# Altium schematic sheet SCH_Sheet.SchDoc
size A; SheetNumber: 1; SheetTotal: 1
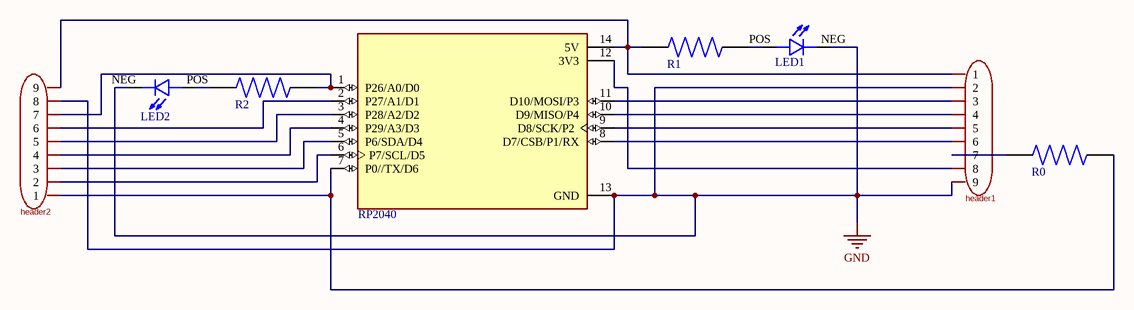
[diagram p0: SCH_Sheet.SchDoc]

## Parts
header1  2.54-1*9P母  [2.54-1*9]  (value not drawn)
header2  2.54-1*9P母  [2.54-1*9]  (value not drawn)
LED1  LHN974_RED_LED_1206  [LED2]  (value not drawn)
LED2  LHN974_RED_LED_1206  [LED2]  (value not drawn)
R0  1k  [1k]  (value not drawn)
R1  1k  [1k]  (value not drawn)
R2  1k  [1k]  (value not drawn)
RP2040  102010428  [102010428]  (value not drawn)

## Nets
GND: header1.2 header1.9 header2.8 LED1.NEG LED2.NEG RP2040.13(GND)
Netheader1_1: header1.1 header2.9 R1.1 RP2040.14(5V)
Netheader1_3: header1.3 RP2040.11(D10/MOSI/P3)
Netheader1_4: header1.4 RP2040.10(D9/MISO/P4)
Netheader1_5: header1.5 RP2040.9(D8/SCK/P2)
Netheader1_6: header1.6 RP2040.8(D7/CSB/P1/RX)
Netheader1_7: header1.7 R0.1
Netheader1_8: header1.8 RP2040.12(3V3)
Netheader2_1: header2.1 R0.2 RP2040.7(P0//TX/D6)
Netheader2_2: header2.2 RP2040.6(P7/SCL/D5)
Netheader2_3: header2.3 RP2040.5(P6/SDA/D4)
Netheader2_4: header2.4 RP2040.4(P29/A3/D3)
Netheader2_5: header2.5 RP2040.3(P28/A2/D2)
Netheader2_6: header2.6 RP2040.2(P27/A1/D1)
Netheader2_7: header2.7 R2.2 RP2040.1(P26/A0/D0)
NetLED1_POS: LED1.POS R1.2
NetLED2_POS: LED2.POS R2.1

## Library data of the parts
header1 header2 = 2.54-1*9: Manufacturer: BOOMELE(博穆精密); Symbol: Header-Female-2.54_1x9; Add into BOM: yes; Holes Structure: 1x9P; Pitch: 2.54mm; Number of Holes: 9P
LED1 LED2 = LED2: 2.6 V Red LED SMD; MP: LHN974 RED LED 1206; MF: Osram
R0-R2 = 1k: Res Thick Film 3.2 x 1.6 mm 6.8K Ohm 1% 0.25W(1/4W) 100ppm/ C Molded SMD Paper T/R; MP: RC1206FR-076K8L
RP2040 = 102010428: RP2040 XIAO RP2040 series ARMÂ® CortexÂ®-M0+ MCU 32-Bit Embedded Evaluation Board; MF: Seeed Technology Co., Ltd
